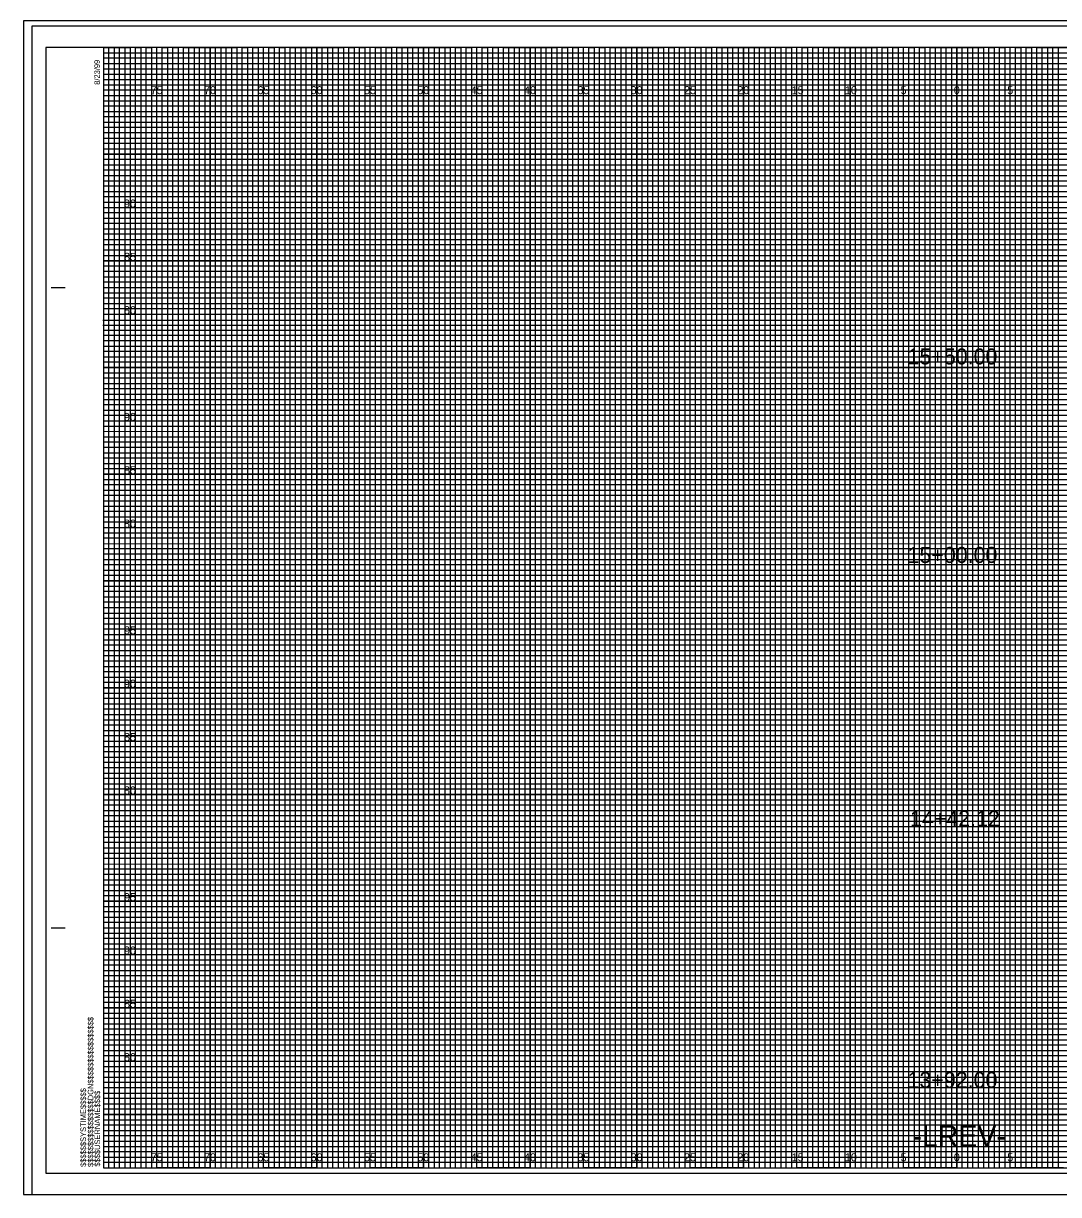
# Model space of a CAD drawing. Extents: x -8 to 533, y -20 to 768.
# Drawn here: x -7.5 to 89.5, y -2.5 to 107.2 of the extents above; entities that cross this region are included whole.
import ezdxf

# ---------------------------------------------------------------- set-up
doc = ezdxf.new("R2010")
doc.units = 0
for name, color, linetype in [('Prop XS Alignment Label', 7, 'Continuous'), ('Prop XS Elevation Labels', 7, 'Continuous'), ('Prop XS Offset Labels', 7, 'Continuous'), ('Prop XS Station Labels', 7, 'Continuous'), ('Sheet Cross Section CELL', 7, 'Continuous'), ('Sheet Cross Section Grid Major CELL', 7, 'Continuous'), ('Sheet Cross Section Grid Middle CELL', 7, 'Continuous'), ('Sheet Cross Section Grid Minor 1 CELL', 7, 'Continuous'), ('Sheet Cross Section Grid Minor 2 CELL', 7, 'Continuous'), ('Sheet Cutting Line CELL', 7, 'Continuous'), ('Sheet DOT Grid CELL', 7, 'Continuous'), ('Sheet Plot Border Inside CELL', 7, 'Continuous'), ('Sheet Plot Border Outside CELL', 7, 'Continuous'), ('WEI Plot Border', 7, 'Continuous')]:
    doc.layers.add(name, color=color, linetype=linetype)

msp = doc.modelspace()

# ---------------------------------------------------------------- linework, layer by layer
at = {"layer": 'Sheet Cross Section CELL'}
for p, q in [((-4.9, 82.5), (-3.65, 82.5)), ((-4.85, 82.5), (-3.6, 82.5)), ((-4.9, 22.5), (-3.65, 22.5)), ((-4.85, 22.5), (-3.6, 22.5)), ((0, 0), (0, 0)), ((0, 0), (0, 0)), ((0, 0), (0, 0)), ((0, 0), (0, 0)), ((0, 0), (0, 0)), ((0, 0), (0, 0)), ((0, 0), (0, 0))]:
    msp.add_line(p, q, dxfattribs=at)
msp.add_lwpolyline([(160, 105), (0, 105), (0, 0), (160, 0)], close=True, dxfattribs=at)
at = {"layer": 'Sheet Cross Section Grid Major CELL'}
for p, q in [((5, 105), (0, 105)), ((5, 0), (5, 105)), ((15, 105), (10, 105)), ((10, 105), (10, 0)), ((15, 0), (15, 105)), ((25, 105), (20, 105)), ((20, 105), (20, 0)), ((25, 0), (25, 105)), ((35, 105), (30, 105)), ((30, 105), (30, 0)), ((35, 0), (35, 105)), ((45, 105), (40, 105)), ((40, 105), (40, 0)), ((45, 0), (45, 105)), ((55, 105), (50, 105)), ((50, 105), (50, 0)), ((55, 0), (55, 105)), ((65, 105), (60, 105)), ((60, 105), (60, 0)), ((65, 0), (65, 105)), ((75, 105), (70, 105)), ((70, 105), (70, 0)), ((75, 0), (75, 105)), ((85, 105), (80, 105)), ((80, 105), (80, 0)), ((85, 0), (85, 105)), ((10, 0), (5, 0)), ((20, 0), (15, 0)), ((30, 0), (25, 0)), ((40, 0), (35, 0)), ((50, 0), (45, 0)), ((60, 0), (55, 0)), ((70, 0), (65, 0)), ((80, 0), (75, 0)), ((90, 0), (85, 0))]:
    msp.add_line(p, q, dxfattribs=at)
for points in [[(0, 100), (160, 100), (160, 95), (0, 95)], [(0, 90), (160, 90), (160, 85), (0, 85)], [(0, 80), (160, 80), (160, 75), (0, 75)], [(0, 70), (160, 70), (160, 65), (0, 65)], [(0, 60), (160, 60), (160, 55), (0, 55)], [(0, 50), (160, 50), (160, 45), (0, 45)], [(0, 40), (160, 40), (160, 35), (0, 35)], [(0, 30), (160, 30), (160, 25), (0, 25)], [(0, 20), (160, 20), (160, 15), (0, 15)], [(0, 10), (160, 10), (160, 5), (0, 5)]]:
    msp.add_lwpolyline(points, dxfattribs=at)
at = {"layer": 'Sheet Cross Section Grid Middle CELL'}
for points in [[(0, 105), (2.5, 105), (2.5, 0), (7.5, 0), (7.5, 105), (12.5, 105), (12.5, 0), (17.5, 0), (17.5, 105), (22.5, 105), (22.5, 0), (27.5, 0), (27.5, 105), (32.5, 105), (32.5, 0), (37.5, 0), (37.5, 105), (42.5, 105), (42.5, 0), (47.5, 0), (47.5, 105), (52.5, 105), (52.5, 0), (57.5, 0), (57.5, 105), (62.5, 105), (62.5, 0), (67.5, 0), (67.5, 105), (72.5, 105), (72.5, 0), (77.5, 0), (77.5, 105), (82.5, 105), (82.5, 0), (87.5, 0), (87.5, 105), (92.5, 105)], [(0, 102.5), (137.5, 102.5)], [(0, 92.5), (160, 92.5), (160, 97.5), (0, 97.5)], [(0, 82.5), (160, 82.5), (160, 87.5), (0, 87.5)], [(0, 72.5), (160, 72.5), (160, 77.5), (0, 77.5)], [(0, 62.5), (160, 62.5), (160, 67.5), (0, 67.5)], [(0, 52.5), (160, 52.5), (160, 57.5), (0, 57.5)], [(0, 42.5), (160, 42.5), (160, 47.5), (0, 47.5)], [(0, 32.5), (160, 32.5), (160, 37.5), (0, 37.5)], [(0, 22.5), (160, 22.5), (160, 27.5), (0, 27.5)], [(0, 12.5), (160, 12.5), (160, 17.5), (0, 17.5)], [(0, 2.5), (160, 2.5), (160, 7.5), (0, 7.5)]]:
    msp.add_lwpolyline(points, dxfattribs=at)
at = {"layer": 'Sheet Cross Section Grid Minor 1 CELL'}
for p, q in [((0, 104.5), (130, 104.5)), ((130, 103.99), (0, 103.99)), ((0, 103.99), (0, 103.5)), ((0, 103.5), (130, 103.5)), ((130, 102.95), (0, 102.95)), ((0, 102.95), (0, 102)), ((0, 102), (160, 102))]:
    msp.add_line(p, q, dxfattribs=at)
for points in [[(0, 101.5), (135, 101.5), (160, 101.5), (160, 101), (0, 101)], [(0, 100.5), (160, 100.5), (160, 99.5), (0, 99.5)], [(0, 99), (160, 99), (160, 98.5), (0, 98.49)], [(0, 98), (160, 98), (160, 97), (0, 97)], [(0, 96.5), (160, 96.5), (160, 96), (0, 96)], [(0, 95.5), (160, 95.5), (160, 94.5), (0, 94.5)], [(0, 94), (160, 94), (160, 93.5), (0, 93.5)], [(0, 93), (160, 93), (160, 92), (0, 92)], [(0, 91.5), (160, 91.5), (160, 91), (0, 91)], [(0, 90.5), (160, 90.5), (160, 89.5), (0, 89.5)], [(0, 89), (160, 89), (160, 88.5), (0, 88.5)], [(0, 88), (160, 88), (160, 86.98), (160, 86.5), (160, 86), (0, 86)], [(0, 87), (160, 87), (160, 86.5), (0, 86.5)], [(0, 85.5), (160, 85.5), (160, 84.5), (0, 84.52)], [(0, 84.52), (160, 84.5), (160, 84), (0, 84)], [(0, 83.5), (160, 83.5), (160, 83), (0, 83)], [(0, 82), (160, 82), (160, 81.5), (0, 81.5)], [(0, 81), (160, 81), (160, 80.5), (0, 80.5)], [(-0.04, 79.45), (160, 79.45), (160, 78.94), (-0.04, 78.94)], [(0, 78.5), (160, 78.5), (160, 78), (0, 78)], [(0, 77), (160, 77), (160, 76.5), (0, 76.5)], [(0, 76), (160, 76), (160, 75.5), (0, 75.5)], [(0, 74.5), (160, 74.5), (160, 74), (0, 74)], [(0, 73.5), (160, 73.5), (160, 73), (0, 73)], [(0, 72), (160, 72), (160, 71.5), (0, 71.5)], [(0, 71), (160, 71), (160, 70.5), (0, 70.5)], [(0, 69.5), (160, 69.5), (160, 68.99), (0, 69)], [(0, 68.5), (160, 68.5), (160, 68), (0, 68)], [(0, 67), (160, 67), (160, 66.5), (0, 66.5)], [(0, 66), (160, 66), (160, 65.5), (0, 65.5)], [(0, 64.5), (160, 64.5), (160, 64), (0, 64)], [(0, 63.5), (160, 63.5), (160, 63), (0, 63)], [(0, 62), (160, 62), (160, 61.5), (0, 61.5)], [(0, 61), (160, 61), (160, 60.5), (0, 60.5)], [(0, 59.5), (160, 59.5), (160, 59), (0, 59)], [(0, 58.5), (160.03, 58.45), (160, 58), (0, 58)], [(0, 57), (160, 57), (160, 56.5), (0, 56.5)], [(0, 56), (160, 56), (160, 55.5), (0, 55.5)], [(0, 54.5), (160, 54.5), (160, 54), (0, 54)], [(0, 53.5), (160, 53.5), (160, 53), (0, 53)], [(0, 52), (160, 52), (160, 51.5), (0, 51.5)], [(0, 51), (160, 51), (160, 50.5), (0, 50.5)], [(0, 49.5), (160, 49.5), (160, 49), (0, 49)], [(0, 48.5), (160, 48.5), (160, 48), (0, 48)], [(0, 47), (160, 47), (160, 46.5), (0, 46.5)], [(0, 46), (160, 46), (160, 45.5), (0, 45.5)], [(0, 44.5), (160, 44.5), (160, 44), (0, 44)], [(0, 43.5), (160, 43.5), (160, 43), (0, 43)], [(0, 42), (160, 42), (160, 41.5), (0, 41.5)], [(0, 41), (160, 41), (160, 40.5), (0, 40.5)], [(0, 39.5), (160, 39.5), (160, 38.99), (0, 39)], [(0, 38.5), (160, 38.5), (160, 38), (0, 38)], [(0, 37), (160, 37), (160, 36.5), (0, 36.5)], [(0, 36), (160, 36), (160, 35.5), (0, 35.5)], [(0, 34.5), (160, 34.5), (160, 34), (0, 34)], [(0, 33.5), (160, 33.5), (160, 33), (0, 33)], [(0, 32), (160, 32), (160, 31.5), (0, 31.5)], [(0, 31), (160, 31), (160, 30.5), (0, 30.5)], [(0, 29.5), (160, 29.5), (160, 29), (0, 29)], [(0, 28.5), (160.03, 28.46), (160, 28), (0, 28)], [(0, 27), (160, 27), (160, 26.5), (0, 26.5)], [(0, 26), (160, 26), (160, 25.5), (0, 25.5)], [(0, 24.5), (160, 24.5), (160, 24), (0, 24)], [(0, 23.5), (160, 23.5), (160, 23), (0, 23)], [(0, 22), (160, 22), (160, 21.5), (0, 21.5)], [(0, 21), (160, 21), (160, 20.5), (0, 20.5)], [(0, 19.5), (160, 19.5), (160, 19), (0, 19)], [(0, 18.5), (160, 18.5), (160, 18), (0, 18)], [(0, 17), (160, 17), (160, 16.5), (0, 16.5)], [(0, 16), (160, 16), (160, 15.5), (0, 15.5)], [(0, 14.5), (160, 14.5), (160, 14), (0, 14)], [(0, 13.5), (160, 13.5), (160, 13), (0, 13)], [(0, 12), (160, 12), (160, 11.5), (0, 11.5)], [(0, 11), (160, 11), (160, 10.5), (0, 10.5)], [(0, 9.5), (160, 9.5), (160, 9), (0, 9)], [(0, 8.5), (160, 8.5), (160, 8), (0, 8)], [(0, 7), (160, 7), (160, 6.5), (0, 6.5)], [(0, 6), (160, 6), (160, 5.5), (0, 5.5)], [(0, 4.5), (160, 4.5), (160, 4), (0, 4)], [(0, 3.5), (160, 3.5), (160, 3), (0, 3)], [(0, 2), (160, 2), (160, 1.5), (0, 1.5)], [(0, 1), (160, 1), (160, 0.5), (0, 0.5)]]:
    msp.add_lwpolyline(points, dxfattribs=at)
at = {"layer": 'Sheet Cross Section Grid Minor 2 CELL'}
for points in [[(0, 0), (0.5, 0), (0.5, 105), (1, 105), (1, 0)], [(1, 0), (1.5, 0), (1.5, 105), (2, 105), (2, 0)], [(2.5, 0), (3, 0), (3, 105), (3.5, 105), (3.5, 0)], [(3.5, 0), (4, 0), (4, 105), (4.5, 105), (4.5, 0)], [(5, 0), (5.5, 0), (5.5, 105), (6, 105), (6, 0)], [(6, 0), (6.5, 0), (6.5, 105), (7, 105), (7, 0)], [(7.5, 0), (8, 0), (8, 105), (8.5, 105), (8.5, 0)], [(8.5, 0), (9, 0), (9, 105), (9.5, 105), (9.5, 0)], [(10, 0), (10.5, 0), (10.5, 105), (11, 105), (11, 0)], [(11, 0), (11.5, 0), (11.5, 105), (12, 105), (12, 0)], [(12.5, 0), (13, 0), (13, 105), (13.5, 105), (13.5, 0)], [(13.5, 0), (14, 0), (14, 105), (14.5, 105), (14.5, 0)], [(15, 0), (15.5, 0), (15.5, 105), (16, 105), (16, 0)], [(16, 0), (16.5, 0), (16.5, 105), (17, 105), (17, 0)], [(17.5, 0), (18, 0), (18, 105), (18.5, 105), (18.5, 0)], [(18.5, 0), (19, 0), (19, 105), (19.5, 105), (19.5, 0)], [(20, 0), (20.5, 0), (20.5, 105), (21, 105), (21, 0)], [(21, 0), (21.5, 0), (21.5, 105), (22, 105), (22, 0)], [(22.5, 0), (23, 0), (23, 105), (23.5, 105), (23.5, 0)], [(23.5, 0), (24, 0), (24, 105), (24.5, 105), (24.5, 0)], [(25, 0), (25.5, 0), (25.5, 105), (26, 105), (26, 0)], [(26, 0), (26.5, 0), (26.5, 105), (27, 105), (27, 0)], [(27.5, 0), (28, 0), (28, 105), (28.5, 105), (28.5, 0)], [(28.5, 0), (29, 0), (29, 105), (29.5, 105), (29.5, 0)], [(30, 0), (30.5, 0), (30.5, 105), (31, 105), (31, 0)], [(31, 0), (31.5, 0), (31.5, 105), (32, 105), (32, 0)], [(32.5, 0), (33, 0), (33, 105), (33.5, 105), (33.5, 0)], [(33.5, 0), (34, 0), (34, 105), (34.5, 105), (34.5, 0)], [(35, 0), (35.5, 0), (35.5, 105), (36, 105), (36, 0)], [(36, 0), (36.5, 0), (36.5, 105), (37, 105), (37, 0)], [(37.5, 0), (38, 0), (38, 105), (38.5, 105), (38.5, 0)], [(38.5, 0), (39, 0), (39, 105), (39.5, 105), (39.5, 0)], [(40, 0), (40.5, 0), (40.5, 105), (41, 105), (41, 0)], [(41, 0), (41.5, 0), (41.5, 105), (42, 105), (42, 0)], [(42.5, 0), (43, 0), (43, 105), (43.5, 105), (43.5, 0)], [(43.5, 0), (44, 0), (44, 105), (44.5, 105), (44.5, 0)], [(45, 0), (45.5, 0), (45.5, 105), (46, 105), (46, 0)], [(46, 0), (46.5, 0), (46.5, 105), (47, 105), (47, 0)], [(47.5, 0), (48, 0), (48, 105), (48.5, 105), (48.5, 0)], [(48.5, 0), (49, 0), (49, 105), (49.5, 105), (49.5, 0)], [(50, 0), (50.5, 0), (50.5, 105), (51, 105), (51, 0)], [(51, 0), (51.5, 0), (51.5, 105), (52, 105), (52, 0)], [(52.5, 0), (53, 0), (53, 105), (53.5, 105), (53.5, 0)], [(53.5, 0), (54, 0), (54, 105), (54.5, 105), (54.5, 0)], [(55, 0), (55.5, 0), (55.5, 105), (56, 105), (56, 0)], [(56, 0), (56.5, 0), (56.5, 105), (57, 105), (57, 0)], [(57.5, 0), (58, 0), (58, 105), (58.5, 105), (58.5, 0)], [(58.5, 0), (59, 0), (59, 105), (59.5, 105), (59.5, 0)], [(60, 0), (60.5, 0), (60.5, 105), (61, 105), (61, 0)], [(61, 0), (61.5, 0), (61.5, 105), (62, 105), (62, 0)], [(62.5, 0), (63, 0), (63, 105), (63.5, 105), (63.5, 0)], [(63.5, 0), (64, 0), (64, 105), (64.5, 105), (64.5, 0)], [(65, 0), (65.5, 0), (65.5, 105), (66, 105), (66, 0)], [(66, 0), (66.5, 0), (66.5, 105), (67, 105), (67, 0)], [(67.5, 0), (68, 0), (68, 105), (68.5, 105), (68.5, 0)], [(68.5, 0), (69, 0), (69, 105), (69.5, 105), (69.5, 0)], [(70, 0), (70.5, 0), (70.5, 105), (71, 105), (71, 0)], [(71, 0), (71.5, 0), (71.5, 105), (72, 105), (72, 0)], [(72.5, 0), (73, 0), (73, 105), (73.5, 105), (73.5, 0)], [(73.5, 0), (74, 0), (74, 105), (74.5, 105), (74.5, 0)], [(75, 0), (75.5, 0), (75.5, 105), (76, 105), (76, 0)], [(76, 0), (76.5, 0), (76.5, 105), (77, 105), (77, 0)], [(77.5, 0), (78, 0), (78, 105), (78.5, 105), (78.5, 0)], [(78.5, 0), (79, 0), (79, 105), (79.5, 105), (79.5, 0)], [(80, 0), (80.5, 0), (80.5, 105), (81, 105), (81, 0)], [(81, 0), (81.5, 0), (81.5, 105), (82, 105), (82, 0)], [(82.5, 0), (83, 0), (83, 105), (83.5, 105), (83.5, 0)], [(83.5, 0), (84, 0), (84, 105), (84.5, 105), (84.5, 0)], [(85, 0), (85.5, 0), (85.5, 105), (86, 105), (86, 0)], [(86, 0), (86.5, 0), (86.5, 105), (87, 105), (87, 0)], [(87.5, 0), (88, 0), (88, 105), (88.5, 105), (88.5, 0)], [(88.5, 0), (89, 0), (89, 105), (89.5, 105), (89.5, 0)]]:
    msp.add_lwpolyline(points, dxfattribs=at)
at = {"layer": 'Sheet Cutting Line CELL'}
for p, q in [((161.65, 107), (-6.7, 107)), ((-6.7, 107), (-6.7, -2.5)), ((-6.7, -2.5), (161.65, -2.5))]:
    msp.add_line(p, q, dxfattribs=at)
at = {"layer": 'Sheet DOT Grid CELL'}
for p, q in [((5, 0), (5, 105)), ((10, 0), (10, 105)), ((15, 0), (15, 105)), ((20, 0), (20, 105)), ((25, 0), (25, 105)), ((30, 0), (30, 105)), ((35, 0), (35, 105)), ((40, 0), (40, 105)), ((45, 0), (45, 105)), ((50, 0), (50, 105)), ((55, 0), (55, 105)), ((60, 0), (60, 105)), ((65, 0), (65, 105)), ((70, 0), (70, 105)), ((75, 0), (75, 105)), ((80, 0), (80, 105)), ((85, 0), (85, 105)), ((0, 100), (160, 100)), ((0, 95), (160, 95)), ((0, 90), (160, 90)), ((0, 85), (160, 85)), ((0, 80), (160, 80)), ((0, 75), (160, 75)), ((0, 70), (160, 70)), ((0, 65), (160, 65)), ((0, 60), (160, 60)), ((0, 55), (160, 55)), ((0, 50), (160, 50)), ((0, 45), (160, 45)), ((0, 40), (160, 40)), ((0, 35), (160, 35)), ((0, 30), (160, 30)), ((0, 25), (160, 25)), ((0, 20), (160, 20)), ((0, 15), (160, 15)), ((0, 10), (160, 10)), ((0, 5), (160, 5))]:
    msp.add_line(p, q, dxfattribs=at)
at = {"layer": 'Sheet Plot Border Inside CELL'}
msp.add_lwpolyline([(-5.4, -0.5), (161.2, -0.5), (161.2, 105), (-5.4, 105)], close=True, dxfattribs=at)
at = {"layer": 'Sheet Plot Border Outside CELL'}
msp.add_lwpolyline([(-6.7, -2.5), (161.65, -2.5), (161.65, 107), (-6.7, 107)], close=True, dxfattribs=at)
at = {"layer": 'WEI Plot Border'}
msp.add_lwpolyline([(-7.5, -2.5), (162.5, -2.5), (162.5, 107.5), (-7.5, 107.5)], close=True, dxfattribs=at)

# ---------------------------------------------------------------- texts
at = {"layer": 'Prop XS Alignment Label'}
msp.add_text('-LREV-', height=2, dxfattribs=at).set_placement((75.84, 2))
at = {"layer": 'Prop XS Elevation Labels'}
for s, p in [('90', (1.93, 90)), ('85', (1.94, 85)), ('80', (1.93, 80)), ('90', (1.93, 70)), ('85', (1.94, 65)), ('80', (1.93, 60)), ('95', (1.94, 50)), ('90', (1.93, 45)), ('85', (1.94, 40)), ('80', (1.93, 35)), ('95', (1.94, 25)), ('90', (1.93, 20)), ('85', (1.94, 15)), ('80', (1.93, 10))]:
    msp.add_text(s, height=0.75, dxfattribs=at).set_placement(p)
at = {"layer": 'Prop XS Offset Labels'}
for s, p in [('75', (4.44, 100.62)), ('70', (9.43, 100.62)), ('65', (14.44, 100.62)), ('60', (19.43, 100.62)), ('55', (24.44, 100.62)), ('50', (29.43, 100.62)), ('45', (34.44, 100.62)), ('40', (39.43, 100.62)), ('35', (44.44, 100.62)), ('30', (49.43, 100.62)), ('25', (54.44, 100.62)), ('20', (59.43, 100.62)), ('15', (64.53, 100.62)), ('10', (69.52, 100.62)), ('5', (74.74, 100.62)), ('0', (79.73, 100.62)), ('0', (79.73, 100.62)), ('5', (84.74, 100.62)), ('75', (4.44, 0.62)), ('70', (9.43, 0.62)), ('65', (14.44, 0.62)), ('60', (19.43, 0.62)), ('55', (24.44, 0.62)), ('50', (29.43, 0.62)), ('45', (34.44, 0.62)), ('40', (39.43, 0.62)), ('35', (44.44, 0.62)), ('30', (49.43, 0.62)), ('25', (54.44, 0.62)), ('20', (59.43, 0.62)), ('15', (64.53, 0.62)), ('10', (69.52, 0.62)), ('5', (74.74, 0.62)), ('0', (79.73, 0.62)), ('0', (79.73, 0.62)), ('5', (84.74, 0.62))]:
    msp.add_text(s, height=0.75, dxfattribs=at).set_placement(p)
at = {"layer": 'Prop XS Station Labels'}
for s, p in [('15+50.00', (75.39, 75.29)), ('15+00.00', (75.39, 56.69)), ('14+42.12', (75.62, 31.99)), ('13+92.00', (75.39, 7.49))]:
    msp.add_text(s, height=1.5, dxfattribs=at).set_placement(p)
at = {"layer": 'Sheet Cross Section CELL'}
for s, p in [('8/23/99', (-0.33, 101.5)), ('$$$$$$$$$$$$$$$$DGN$$$$$$$$$$$$$$$$', (-0.94, 0.09)), ('$$$$$$SYSTIME$$$$$', (-1.63, 0.09)), ('$$$$USERNAME$$$$', (-0.31, 0.12))]:
    msp.add_text(s, height=0.525, rotation=90, dxfattribs=at).set_placement(p)

doc.saveas('drawing.dxf')
